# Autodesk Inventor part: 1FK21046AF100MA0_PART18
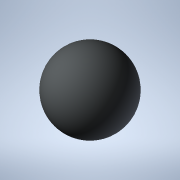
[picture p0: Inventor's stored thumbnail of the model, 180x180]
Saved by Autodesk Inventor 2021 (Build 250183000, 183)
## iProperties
Created: 2025-04
Part Number: 1FK21046AF100MA0_PART18
Material: Generic
Catalog Web Link: www.3dfindit.com
Description: -Servo synchronous motor
Document SubType Name: Modeling
Designer: psAdmin
Mass: 0.137258 g
Surface Area: 1.2868 cm^2
Volume: 0.137258 cm^3
Density: 1 g/cm^3
Appearance: PSOLRGB-212-217-219
Category: PARTsolutions
Title: 1FK21046AF100MA0_PART18
Author: Cadenas PARTsolutions
Comments: Servo synchronous motor
Sending System: PARTsolutions
Preprocessor: ST-DEVELOPER v19.3
PSOL_IDENT_0: {$CADENAS_DATA/23d-libs/siemens_ag/_cat_/4f/2b/1fk21046af100ma0.prj},216 {VTYP=3D},{NB=1FK21046AF100
PSOL_IDENT_1: MA0_PART18},{LINA=1FK21046AF100MA0_PART18},{NN=1FK21046AF100MA0_PART18},{NOPRJ=TRUE},{DATE=19.08.202
PSOL_IDENT_2: 5 14:00:37},{GEOMDATE=30.07.2025 02:01:06},{VERSION=},{LINEID=10},{WBVAR=},{WBNUMERIC=}  {NB=1FK2104
PSOL_IDENT_3: 6AF100MA0_PART18},{LINA=1FK21046AF100MA0_PART18},{KT=DUMMY},{PREVIEW=../../../_pool_/cb/72/p_d211_xx
PSOL_IDENT_4: _00434j.png},{DESCSHORT=SIMOTICS S-1FK2 HD, SINAMICS S210 3AC 400V-480V, 3.2 Nm, 3000 rpm},{DESCLONG=
PSOL_IDENT_5: SIMOTICS S-1FK2 HD servo motor M0=3.2 Nm; PN = 1 kW at nN=3000 rpm (380-480 V); PN = 0.5 kW at nN=15
PSOL_IDENT_6: 00 rpm (200-240 V); with holding brake; degree of protection IP64; cylindrical shaft D19x40mm; absol
PSOL_IDENT_7: ute encoder 22-bit + 12-bit multiturn (encoder AM22DQC); with OCC interface; plug size M17, rotatabl
PSOL_IDENT_8: e; SIMOTICS S-1FK2 servomotorfor a wide range of uses in industrial environments. SIMOTICS S‑1FK2 se
PSOL_IDENT_9: rvomotors are compact synchronous motors with a high dynamic performance that set themselves apart a
PSOL_IDENT_10: s a result of their high power density, degree of protection and overload capability. The motors are
PSOL_IDENT_11: available in two variants: as High Dynamic variant (highest dynamic performance as a result of the
PSOL_IDENT_12: low intrinsic moment of inertia for applications demanding a high dynamic performance with low moved
PSOL_IDENT_13: masses) - and as Compact variant (precise and stable closed-loop control for medium up to large mov
PSOL_IDENT_14: ed masses as a result of a medium intrinsic moment of inertia). SIMOTICSS‑1FK2 servomotors fully exp
PSOL_IDENT_15: loit their strengths in a system with the SINAMICSS210 frequency converter and simple connection usi
PSOL_IDENT_16: ng the one cable connection (OCC). Advantages include the short control and positioning times, fast
PSOL_IDENT_17: and precise correction of disturbing quantities as well as stable control with a high dynamic perfor
PSOL_IDENT_18: mance. The servo motors can be configured to address a wide range of requirements. For example with
PSOL_IDENT_19: and without holding brake, IP64 or IP65 degree of protection, singleturn or multiturn absolute encod
PSOL_IDENT_20: ers - to name just a few. Further, the servomotors are available in different shaft heights extendin
PSOL_IDENT_21: g from 20 to 100. A shaft sealing ring is available to achieve an IP65 degree of protection and for
PSOL_IDENT_22: subsequent mounting at the motor or as spare part. SIMOTICS - the optimum motor for each and every m
PSOL_IDENT_23: otion control application.},{INTNO=195125049673},{SUPPLIERALTNO=1FK2104-6AF10-0MA0},{MANUID=1FK21046
PSOL_IDENT_24: AF100MA0},{MANUNAME=Siemens},{MANUTYPEDESC=Synchronous motor 1FK2-HD 3.2 NM},{AAU732=SIMOTICS},{AAO0
PSOL_IDENT_25: 57=S-1FK2},{AAU734=SIMOTICS S-1FK2 HD servo motor M0=3.2 Nm; PN = 1 kW at nN=3000 rpm (380-480 V); P
PSOL_IDENT_26: N = 0.5 kW at nN=1500 rpm (200-240 V); with holding brake; degree of protection IP64; cylindrical sh
PSOL_IDENT_27: aft D19x40mm; absolute encoder 22-bit + 12-bit multiturn (encoder AM22DQC); with OCC interface; plug
PSOL_IDENT_28: size M17, rotatable;},{AAW338=Synchronous motor 1FK2-HD 3.2 NM},{AAO742=SIMOTICS},{AAO663=404294869
PSOL_IDENT_29: 4534},{NOCUPEROU=1},{PRICEQUANTITY=1},{QUANTITYMIN=1},{QUANTITYINT=1},{CTN=85015220},{COO=DE},{AAO67
PSOL_IDENT_30: 6=1FK2104-6AF10-0MA0},{AAO677=Siemens AG},{ORDERUNIT=C62},{CONTENTUNIT=C62}
NB: 1FK21046AF100MA0_PART18
NT: Servo synchronous motor
NBSYN: $MANUID._PART18
LINA: 1FK21046AF100MA0_PART18
CATALOG: SIEMENS
PREVIEW: ../../../_pool_/cb/72/p_d211_xx_00434j.png
DESCSHORT: SIMOTICS S-1FK2 HD, SINAMICS S210 3AC 400V-480V, 3.2 Nm, 3000 rpm
DESCLONG: SIMOTICS S-1FK2 HD servo motor M0=3.2 Nm; PN = 1 kW at nN=3000 rpm (380-480 V); PN = 0.5 kW at nN=1500 rpm (200-240 V); with holding brake; degree of protection
INTNO: 195125049673
SUPPLIERALTNO: 1FK2104-6AF10-0MA0
MANUID: 1FK21046AF100MA0
MANUNAME: Siemens
MANUTYPEDESC: Synchronous motor 1FK2-HD 3.2 NM
AAU732: SIMOTICS
AAO057: S-1FK2
AAU734: SIMOTICS S-1FK2 HD servo motor M0=3.2 Nm; PN = 1 kW at nN=3000 rpm (380-480 V); PN = 0.5 kW at nN=1500 rpm (200-240 V); with holding brake; degree of protection
AAW338: Synchronous motor 1FK2-HD 3.2 NM
AAO742: SIMOTICS
AAO663: 4042948694534.0
NOCUPEROU: 1
PRICEQUANTITY: 1
QUANTITYMIN: 1
QUANTITYINT: 1
CTN: 85015220
COO: DE
ARTICLENO: 1FK21046AF100MA0_PART18
BOMINFO: 1FK21046AF100MA0_PART18
CREATOR: CADENAS GmbH
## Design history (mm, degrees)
feature "2025_04_17_14_59_39_0177"
body "Solid1"
